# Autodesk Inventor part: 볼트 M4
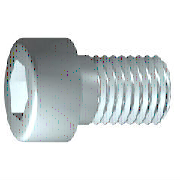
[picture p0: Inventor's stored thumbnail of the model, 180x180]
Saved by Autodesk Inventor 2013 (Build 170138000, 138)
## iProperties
IsCustomPart: 0
Created: 2018-09
Part Number: 볼트 M4
Material: 스테인리스강
Description: 6각머리 태핑 나사
Document SubType Name: Modeling
Standard: KS B 1003
Standards Organization: KS
Language: ko-KR
Size Designation: M 4 x 10
Categories: <MemberInstance><Categories><Category DisplayName="조임쇠" InternalName="e4da775c-781d-43d5-af7c-5136215cf5a6" Mnemonic="FSTN"><Category DisplayName="볼트" InternalN
Density: 1 g/cm^3
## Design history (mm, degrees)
sketch "스케치1"
  geometry: L1 (-1, 0)-(10, 0); L2 (10, 0)-(10, 2); L3 (10, 2)-(1.75, 2); L4 (1.75, 2)-(1.32, 2); L5 (1.32, 2)-(0, 2); L6 (0, 2)-(0, 3.5); L7 (0, 3.5)-(-4, 3.5); L8 (-4, 3.5)-(-4, 1.732); L9 (-4, 1.732)-(-2, 1.732); L10 (-2, 1.732)-(-1, 0); L11 (-6.8, 0)-(12.8, 0) reference; L12 (0, -0.7)-(0, 4.2) reference; L13 (1.75, 2)-(0, 2)
  constraints: 22 end point, 6 parallel, 2 collinear, 2 perpendicular, 1 horizontal, 1 point on line
  dimensions: "d1" = 8.25 distance from line of L3.end L2 (= GEL); "d2" = 0.42952 distance of L4.end L3.end (computed from GAL); "d3" = 4 distance between parallel lines of L8 L6 (= KOH); "d4" = 2 distance of L8.end L9.end (= INTI); "d5" = 60 deg angle of L10 L1; "d6" = 4 diameter of L3 L1 (= GD); "d7" = 4 diameter of L5 L1 (= BDM); "d8" = 3.4641 diameter of L9 L1 (= 1.1547 x SW); "d9" = 7 diameter of L7 L1 (= KOD); "d26" = 10 distance between parallel lines of L12 L2 (= NLG)
revolve "본체" sketch "스케치1" stored, may be unused: angle "d10" = 90 deg
sketch "스케치2"
  geometry: L1 (0, -4.9)-(0, 4.9) reference; L2 (-4.9, 0)-(4.9, 0) reference; L3 (1.732, 0)-(0.866, -1.5); L4 (0.866, -1.5)-(-0.866, -1.5); L5 (-0.866, -1.5)-(-1.732, 0); L6 (-1.732, 0)-(-0.866, 1.5); L7 (-0.866, 1.5)-(0.866, 1.5); L8 (0.866, 1.5)-(1.732, 0); 2 further points
  constraints: 12 end point, 1 coincident, 1 horizontal alignment, 1 point on line, 12 other
extrude "슬롯" join sketch "스케치2" stored distance "d11" = 10; taper "d12" = 0 deg
workplane "Work Plane1"
fillet "Fillet2" dims "d30" = 0.1 (= R)
body "Solid1"
fillet "모깎기1" dims "d17" = 0.4 (= RR)
feature "스레드" dims "d13" = 8.25 (= GEL), "d14" = 0
chamfer "모따기1" distance "d15" = 0.42941 (= -0.5 x SPD + 0.5 x GD); stored, may be unused: second distance "d16" = 0.42941 (= GUL), angle "d27" = 45 deg
other parameters: "GD" = 4 (= NND) [user parameter; used in 2 equation terms], "NLG" = 10 [user parameter; used in 1 equation term], "GEL" = 8.25 [user parameter; used in 2 equation terms], "KOD" = 7 [user parameter; used in 1 equation term], "KOH" = 4 [user parameter; used in 1 equation term], "INTI" = 2 [user parameter; used in 1 equation term], "GAL" = 0.42941 (= 0.61345 x PTC) [user parameter; used in 1 equation term], "GUL" = 0.42941 (= 0.61345 x PTC) [user parameter; used in 1 equation term], "BDM" = 4 (= NND) [user parameter; used in 1 equation term], "SW" = 3 [user parameter; used in 2 equation terms], "RR" = 0.4 [user parameter; used in 1 equation term], "SPD" = 3.14117 (= NND - 1.2269 x PTC) [user parameter; used in 1 equation term], "d19" = 0, "d28" = 0, "d29" = 0, "R" = 0.1 [user parameter; used in 1 equation term], "PHH" = 0.2 [user parameter], "GD1" = 3.14117 (= THREADDIA - 1.2269 x PTC) [user parameter], "THREADDIA" = 4 [user parameter; used in 1 equation term], "FAWI" = 45 deg [user parameter], "TPU" = 14.28571 (computed from PTC) [user parameter], "PTC" = 0.7 [user parameter; used in 5 equation terms], "NND" = 4 [user parameter; used in 3 equation terms], "TOA" = 30 deg [user parameter], "E0" = 3.465 (= 1.155 x SW) [user parameter]
